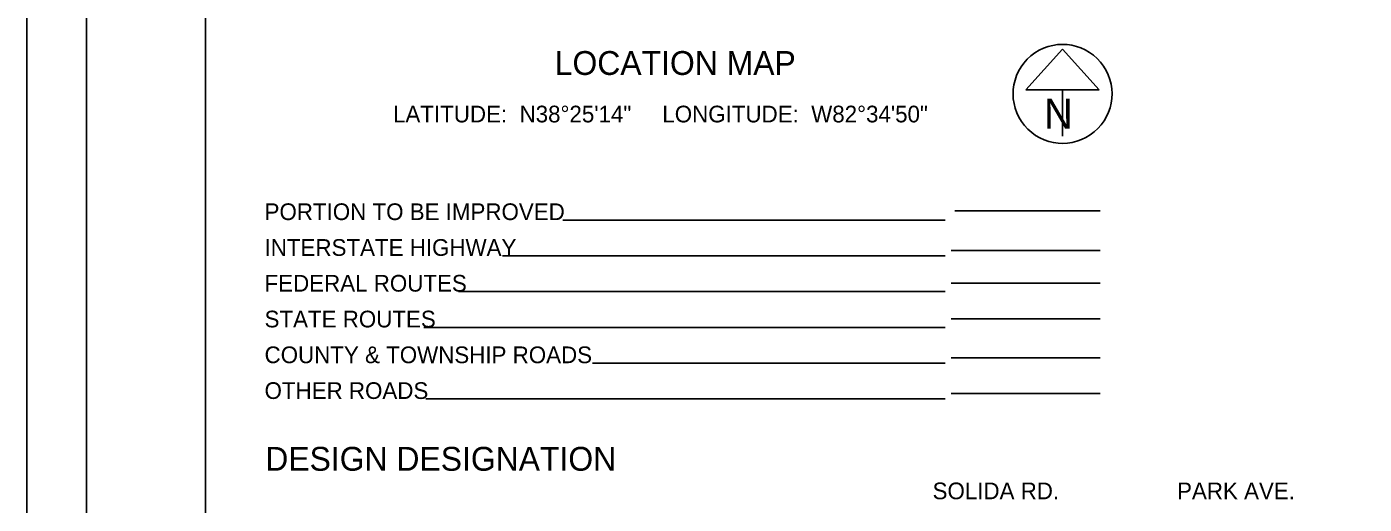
# Model space of a CAD drawing. Extents: x 0 to 45.4, y -2.2 to 22.
# Drawn here: x 0 to 11.21, y 9.99 to 14 of the extents above; entities that cross this region are included whole.
import ezdxf

# ---------------------------------------------------------------- set-up
doc = ezdxf.new("R2010")
doc.units = 0
for name, color, linetype in [('SH_Border', 7, 'Continuous'), ('SH_Cut_Line', 7, 'Continuous'), ('SH_Data', 7, 'Continuous'), ('SH_Text', 7, 'Continuous')]:
    doc.layers.add(name, color=color, linetype=linetype)

msp = doc.modelspace()

# ---------------------------------------------------------------- linework, layer by layer
at = {"layer": 'SH_Border'}
for points in [[(0.5, 21.5), (1.5, 21.5), (1.5, 0.5), (0.5, 0.5)], [(1.5, 21.5), (33.5, 21.5), (33.5, 0.5), (1.5, 0.5)]]:
    msp.add_lwpolyline(points, close=True, dxfattribs=at)
at = {"layer": 'SH_Cut_Line'}
msp.add_lwpolyline([(0, 0), (34, 0), (34, 22), (0, 22)], close=True, dxfattribs=at)
at = {"layer": 'SH_Data'}
for p, q in [((8.685, 13.809), (8.377, 13.468)), ((8.992, 13.468), (8.685, 13.809)), ((8.377, 13.468), (8.992, 13.468)), ((8.685, 13.468), (8.685, 13.081)), ((8.685, 13.435), (8.685, 13.435)), ((8.685, 13.435), (8.685, 13.435)), ((7.783, 12.455), (9, 12.455)), ((7.7, 12.377), (4.494, 12.377)), ((9, 12.121), (7.75, 12.121)), ((7.7, 12.077), (3.99, 12.077)), ((7.7, 11.777), (3.619, 11.777)), ((9, 11.849), (7.75, 11.849)), ((7.7, 11.477), (3.329, 11.477)), ((9, 11.549), (7.75, 11.549)), ((9, 11.222), (7.75, 11.222)), ((7.7, 11.177), (4.745, 11.177)), ((9, 10.922), (7.75, 10.922)), ((7.7, 10.877), (3.347, 10.877))]:
    msp.add_line(p, q, dxfattribs=at)
msp.add_arc((8.685, 13.435), 0.415, 129.7798, 129.7633, dxfattribs=at)

# ---------------------------------------------------------------- texts
for s, height, p in [('N', 0.25, (8.529, 13.144)), ('DESIGN DESIGNATION', 0.2, (2, 10.275))]:
    msp.add_text(s, height=height, dxfattribs=at).set_placement(p)
at = {"layer": 'SH_Text'}
for s, height, p in [('LOCATION MAP', 0.2, (4.427, 13.594)), ('LATITUDE:  N38°25\'14"     LONGITUDE:  W82°34\'50"', 0.14, (3.071, 13.196)), ('PORTION TO BE IMPROVED', 0.14, (1.994, 12.377)), ('INTERSTATE HIGHWAY', 0.14, (1.994, 12.077)), ('FEDERAL ROUTES', 0.14, (1.994, 11.777)), ('STATE ROUTES', 0.14, (1.994, 11.477)), ('COUNTY & TOWNSHIP ROADS', 0.14, (1.994, 11.177)), ('OTHER ROADS', 0.14, (1.994, 10.877)), ('SOLIDA RD.', 0.14, (7.595, 10.036)), ('PARK AVE.', 0.14, (9.645, 10.036))]:
    msp.add_text(s, height=height, dxfattribs=at).set_placement(p)

doc.saveas('drawing.dxf')
